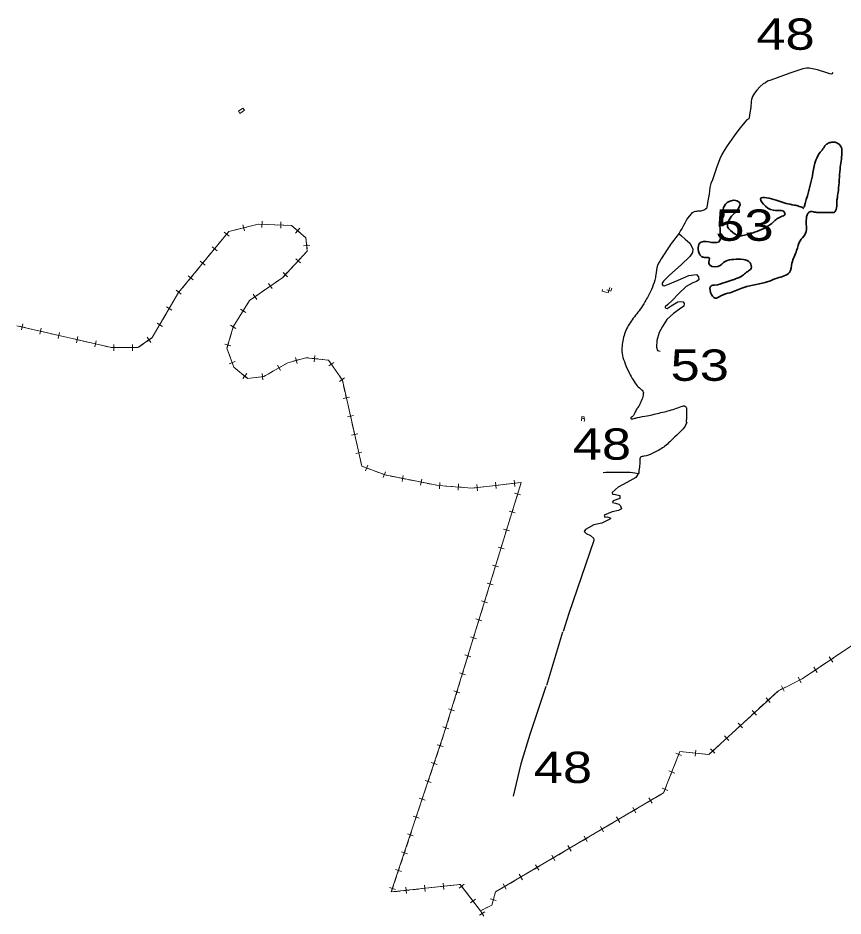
# Model space of a CAD drawing. Extents: x 476989 to 498418, y 4381813 to 4416555.
# Drawn here: x 485528 to 486843, y 4382275 to 4383707 of the extents above; entities that cross this region are included whole.
import ezdxf

# ---------------------------------------------------------------- set-up
doc = ezdxf.new("R2010")
doc.units = 0
doc.header["$LTSCALE"] = 20
doc.linetypes.add('MEDIUM_DASHED', pattern=[4.5, 3, -1.5])
for name, color, linetype, lineweight in [('13', 7, 'Continuous', 13), ('34', 7, 'Continuous', 13), ('48', 7, 'MEDIUM_DASHED', 13), ('6', 7, 'Continuous', 25)]:
    doc.layers.add(name, color=color, linetype=linetype, lineweight=lineweight)

msp = doc.modelspace()

# ---------------------------------------------------------------- linework, layer by layer
at = {"layer": '13', "lineweight": 35}
msp.add_spline([(486780.88, 4383404.79), (486794.13, 4383455.03), (486806.75, 4383492.74), (486812.33, 4383499.64), (486814.71, 4383503.51), (486819.41, 4383506.81), (486825.21, 4383508.61), (486829.49, 4383508.62), (486831.66, 4383508.22), (486834.79, 4383506.67), (486839.23, 4383502.48), (486841.25, 4383491.57), (486838.33, 4383465.65), (486835.59, 4383431.7), (486834, 4383420.31), (486833.25, 4383414.77), (486832.97, 4383406.37), (486832.3, 4383401.5), (486829.47, 4383397.12), (486823.83, 4383396.67), (486809.94, 4383396.27), (486802.97, 4383396.6), (486796, 4383397.37), (486791.44, 4383398.19), (486788.79, 4383396.8), (486785.88, 4383392.64), (486784.6, 4383386.95), (486784.53, 4383376.98), (486784.84, 4383372.17), (486782.2, 4383361.03), (486774.71, 4383351.45), (486769.08, 4383335.85), (486761.59, 4383315.77), (486757.7, 4383301.05), (486738.21, 4383291.87), (486723.87, 4383286.22), (486684.72, 4383277.1), (486662.99, 4383268.56), (486648.14, 4383263.67), (486639.3, 4383259.75), (486632.91, 4383279.8), (486638.33, 4383280.62), (486654.82, 4383284.96), (486667.34, 4383289.06), (486684.49, 4383297.14), (486691.09, 4383302.53), (486696.41, 4383307.18), (486694.82, 4383316.43), (486684.24, 4383321.46), (486669.01, 4383321.68), (486655.38, 4383318.57), (486643.48, 4383310.34), (486629.22, 4383315.27), (486629.5, 4383324.04), (486622.3, 4383324.82), (486616.85, 4383326.7), (486612.21, 4383337.87), (486614.37, 4383347.45), (486644.42, 4383349.27), (486649.2, 4383384.92), (486651.66, 4383388.63), (486652.89, 4383395.9), (486652.14, 4383401.38), (486671.78, 4383415.81), (486678.55, 4383411.44), (486675.33, 4383401.28), (486669.84, 4383395.35), (486659.1, 4383373.67), (486670.12, 4383362.71), (486675.25, 4383359.48), (486683.36, 4383359.82), (486702.12, 4383364.88), (486729.49, 4383379.19), (486744.12, 4383389.71), (486750.48, 4383393.52), (486749.77, 4383396.53), (486731.96, 4383399.94), (486712.51, 4383419.8), (486725.33, 4383419.24), (486752.3, 4383411.05), (486765.39, 4383408.24), (486770.85, 4383407.04), (486780.7, 4383403.07)], degree=3, dxfattribs=at)
at = {"layer": '34'}
for p, q in [((485882.86, 4383370.82), (485892.55, 4383373.29)), ((485886.47, 4383376.9), (485888.94, 4383367.21)), ((485897.4, 4383374.53), (485907.09, 4383377)), ((485911.95, 4383377.96), (485921.94, 4383377.59)), ((485917.13, 4383382.77), (485916.76, 4383372.78)), ((485926.94, 4383377.4), (485936.93, 4383377.02)), ((485941.92, 4383376.83), (485951.91, 4383376.46)), ((485947.1, 4383381.64), (485946.73, 4383371.65)), ((485856.63, 4383364.92), (485864.34, 4383358.56)), ((485857.31, 4383357.88), (485863.67, 4383365.6)), ((485868.34, 4383367.11), (485878.03, 4383369.58)), ((485969.96, 4383370.82), (485977.5, 4383364.26)), ((485977.01, 4383371.31), (485970.45, 4383363.77)), ((485847.77, 4383346.32), (485854.13, 4383354.03)), ((485993.15, 4383344.13), (485983.2, 4383343.18)), ((485987.7, 4383348.63), (485988.65, 4383338.68)), ((485828.69, 4383323.18), (485835.05, 4383330.9)), ((485837.55, 4383341.78), (485845.26, 4383335.42)), ((485838.22, 4383334.75), (485844.59, 4383342.46)), ((485988.11, 4383334.04), (485981.31, 4383326.71)), ((485818.47, 4383318.65), (485826.18, 4383312.29)), ((485819.14, 4383311.61), (485825.5, 4383319.32)), ((485978.17, 4383315.99), (485970.84, 4383322.8)), ((485977.91, 4383323.06), (485971.11, 4383315.73)), ((485809.6, 4383300.05), (485815.97, 4383307.76)), ((485957.76, 4383294.01), (485950.44, 4383300.82)), ((485957.5, 4383301.08), (485950.7, 4383293.75)), ((485967.7, 4383312.07), (485960.9, 4383304.74)), ((485799.38, 4383295.51), (485807.1, 4383289.15)), ((485800.06, 4383288.47), (485806.42, 4383296.19)), ((485946.74, 4383290.73), (485938.54, 4383285)), ((485780.3, 4383272.38), (485788.02, 4383266.01)), ((485790.52, 4383276.91), (485796.89, 4383284.62)), ((485922.15, 4383273.56), (485913.95, 4383267.83)), ((485934.45, 4383282.15), (485926.25, 4383276.42)), ((485933.21, 4383275.18), (485927.49, 4383283.38)), ((485774.05, 4383251.95), (485779.09, 4383260.59)), ((485909.86, 4383264.98), (485901.66, 4383259.25)), ((485908.62, 4383258.02), (485902.9, 4383266.22)), ((485764.7, 4383245.83), (485773.33, 4383240.79)), ((485766.5, 4383238.99), (485771.54, 4383247.63)), ((485889.47, 4383243.84), (485884.21, 4383235.33)), ((485758.94, 4383226.05), (485763.98, 4383234.68)), ((485881.57, 4383231.08), (485876.31, 4383222.58)), ((485891.09, 4383236.95), (485882.59, 4383242.22)), ((485529.63, 4383215.16), (485539.37, 4383212.9)), ((485535.63, 4383218.9), (485533.37, 4383209.16)), ((485749.59, 4383219.93), (485758.22, 4383214.89)), ((485751.39, 4383213.09), (485756.42, 4383221.73)), ((485875.3, 4383211.45), (485866.8, 4383216.72)), ((485544.24, 4383211.77), (485553.99, 4383209.51)), ((485558.85, 4383208.39), (485568.59, 4383206.13)), ((485564.85, 4383212.13), (485562.59, 4383202.39)), ((485573.46, 4383205), (485583.2, 4383202.74)), ((485588.06, 4383201.61), (485597.8, 4383199.36)), ((485594.06, 4383205.36), (485591.8, 4383195.61)), ((485743.83, 4383200.14), (485748.87, 4383208.78)), ((485868.21, 4383204.5), (485865.39, 4383194.91)), ((485602.67, 4383198.23), (485612.42, 4383195.97)), ((485617.28, 4383194.84), (485627.02, 4383192.58)), ((485623.28, 4383198.58), (485621.02, 4383188.84)), ((485631.89, 4383191.46), (485641.63, 4383189.2)), ((485646.49, 4383188.07), (485656.23, 4383185.81)), ((485652.49, 4383191.81), (485650.23, 4383182.07)), ((485680.67, 4383186), (485680.67, 4383176)), ((485710.66, 4383186), (485710.66, 4383176)), ((485720.37, 4383181.95), (485728.58, 4383187.66)), ((485732.67, 4383190.51), (485740.88, 4383196.22)), ((485733.92, 4383197.47), (485739.63, 4383189.26)), ((485867.36, 4383183.91), (485857.77, 4383186.74)), ((485863.98, 4383190.12), (485861.16, 4383180.53)), ((485661.11, 4383184.68), (485670.85, 4383182.43)), ((485690.67, 4383181), (485700.67, 4383181)), ((485705.66, 4383181), (485715.66, 4383181)), ((485862.53, 4383175.82), (485865.97, 4383166.43)), ((485874.11, 4383158.78), (485864.72, 4383155.33)), ((485867.69, 4383161.75), (485871.13, 4383152.36)), ((485966.62, 4383159.38), (485976.26, 4383162.04)), ((485970.11, 4383165.53), (485972.77, 4383155.89)), ((485995.79, 4383164.02), (486005.73, 4383162.92)), ((486001.31, 4383168.44), (486000.21, 4383158.5)), ((486010.7, 4383162.37), (486020.64, 4383161.26)), ((486031.43, 4383157.56), (486023.19, 4383151.89)), ((486024.48, 4383158.85), (486030.15, 4383150.61)), ((485873.92, 4383148.43), (485881.66, 4383142.09)), ((485926.81, 4383138.94), (485935.46, 4383143.95)), ((485939.78, 4383146.45), (485948.44, 4383151.46)), ((485941.6, 4383153.29), (485946.61, 4383144.63)), ((486032.98, 4383146.48), (486038.64, 4383138.24)), ((485885.53, 4383138.93), (485893.27, 4383132.6)), ((485892.56, 4383139.64), (485886.23, 4383131.9)), ((485898.02, 4383132.46), (485907.96, 4383133.61)), ((485917.31, 4383139.72), (485918.46, 4383129.79)), ((486048.42, 4383132.84), (486040.18, 4383127.18)), ((486046.94, 4383120.44), (486049.14, 4383110.69)), ((486056.22, 4383102.05), (486046.47, 4383099.84)), ((486050.24, 4383105.82), (486052.45, 4383096.07)), ((486053.55, 4383091.19), (486055.76, 4383081.44)), ((486062.84, 4383072.8), (486053.09, 4383070.59)), ((486056.86, 4383076.57), (486059.07, 4383066.82)), ((486060.17, 4383061.94), (486062.38, 4383052.19)), ((486069.46, 4383043.55), (486059.71, 4383041.34)), ((486063.48, 4383047.32), (486065.69, 4383037.57)), ((486066.79, 4383032.69), (486069, 4383022.94)), ((486076.08, 4383014.3), (486066.33, 4383012.09)), ((486070.1, 4383018.07), (486072.31, 4383008.32)), ((486073.41, 4383003.44), (486075.62, 4382993.69)), ((486079.05, 4382990.85), (486088.4, 4382987.31)), ((486085.49, 4382993.75), (486081.95, 4382984.4)), ((486093.08, 4382985.54), (486102.43, 4382982)), ((486113.54, 4382983.14), (486110, 4382973.79)), ((486121.52, 4382976.3), (486131.32, 4382974.34)), ((486136.22, 4382973.36), (486146.02, 4382971.4)), ((486142.1, 4382977.28), (486140.14, 4382967.47)), ((486171.51, 4382971.4), (486169.55, 4382961.59)), ((486150.93, 4382970.41), (486160.73, 4382968.45)), ((486165.63, 4382967.47), (486175.43, 4382965.51)), ((486180.33, 4382964.53), (486190.14, 4382962.57)), ((486200.34, 4382965.84), (486199.6, 4382955.87)), ((486209.94, 4382960.12), (486219.91, 4382959.38)), ((486224.89, 4382959.01), (486234.86, 4382958.27)), ((486230.25, 4382963.63), (486229.51, 4382953.65)), ((486239.85, 4382957.9), (486249.82, 4382957.16)), ((486254.79, 4382957.32), (486264.72, 4382958.47)), ((486259.18, 4382962.86), (486260.33, 4382952.93)), ((486269.69, 4382959.04), (486279.62, 4382960.19)), ((486284.58, 4382960.76), (486294.51, 4382961.91)), ((486288.97, 4382966.3), (486290.12, 4382956.37)), ((486299.48, 4382962.48), (486309.42, 4382963.62)), ((486314.37, 4382964.2), (486324.31, 4382965.34)), ((486318.77, 4382969.74), (486319.91, 4382959.8)), ((486329.13, 4382946.12), (486319.57, 4382949.05)), ((486325.82, 4382952.37), (486322.89, 4382942.81)), ((486321.42, 4382938.03), (486318.49, 4382928.47)), ((486320.34, 4382917.45), (486310.78, 4382920.38)), ((486317.02, 4382923.7), (486314.09, 4382914.14)), ((486312.63, 4382909.36), (486309.69, 4382899.8)), ((486311.54, 4382888.78), (486301.98, 4382891.71)), ((486308.23, 4382895.02), (486305.3, 4382885.46)), ((486303.83, 4382880.68), (486300.9, 4382871.12)), ((486302.75, 4382860.11), (486293.19, 4382863.04)), ((486299.44, 4382866.35), (486296.5, 4382856.79)), ((486295.04, 4382852.01), (486292.1, 4382842.45)), ((486293.95, 4382831.44), (486284.39, 4382834.37)), ((486290.64, 4382837.68), (486287.71, 4382828.12)), ((486286.24, 4382823.34), (486283.31, 4382813.78)), ((486285.16, 4382802.76), (486275.6, 4382805.7)), ((486281.85, 4382809.01), (486278.91, 4382799.45)), ((486277.45, 4382794.67), (486274.51, 4382785.11)), ((486276.37, 4382774.09), (486266.81, 4382777.02)), ((486273.05, 4382780.34), (486270.12, 4382770.78)), ((486268.65, 4382766), (486265.72, 4382756.44)), ((486267.57, 4382745.42), (486258.01, 4382748.35)), ((486264.26, 4382751.67), (486261.32, 4382742.11)), ((486259.86, 4382737.33), (486256.93, 4382727.77)), ((486258.78, 4382716.75), (486249.22, 4382719.68)), ((486255.46, 4382723), (486252.53, 4382713.44)), ((486251.06, 4382708.65), (486248.13, 4382699.09)), ((486249.98, 4382688.08), (486240.42, 4382691.01)), ((486246.67, 4382694.32), (486243.74, 4382684.76)), ((486828.14, 4382686.56), (486819.83, 4382681)), ((486826.77, 4382679.63), (486821.2, 4382687.94)), ((486840.6, 4382694.9), (486832.29, 4382689.34)), ((486242.27, 4382679.98), (486239.34, 4382670.42)), ((486801.84, 4382662.94), (486796.28, 4382671.25)), ((486815.67, 4382678.22), (486807.36, 4382672.66)), ((486241.19, 4382659.41), (486231.63, 4382662.34)), ((486237.87, 4382665.65), (486234.94, 4382656.09)), ((486790.75, 4382661.54), (486782.44, 4382655.97)), ((486803.22, 4382669.88), (486794.91, 4382664.32)), ((486233.47, 4382651.31), (486230.54, 4382641.75)), ((486749.26, 4382633.04), (486744.79, 4382641.98)), ((486764.9, 4382646.45), (486755.96, 4382641.98)), ((486776.08, 4382646.45), (486771.61, 4382655.4)), ((486232.39, 4382630.73), (486222.83, 4382633.67)), ((486229.08, 4382636.98), (486226.15, 4382627.42)), ((486738.42, 4382632.55), (486731.05, 4382625.78)), ((486751.49, 4382639.75), (486742.55, 4382635.28)), ((486224.68, 4382622.64), (486221.75, 4382613.08)), ((486727.38, 4382622.4), (486720.02, 4382615.64)), ((486727.08, 4382615.34), (486720.32, 4382622.7)), ((486223.6, 4382602.06), (486214.04, 4382605)), ((486220.28, 4382608.31), (486217.35, 4382598.75)), ((486705.3, 4382602.11), (486697.93, 4382595.35)), ((486705, 4382595.05), (486698.23, 4382602.41)), ((486716.34, 4382612.25), (486708.97, 4382605.49)), ((486215.89, 4382593.97), (486212.95, 4382584.41)), ((486694.25, 4382591.96), (486686.89, 4382585.2)), ((486214.8, 4382573.39), (486205.24, 4382576.32)), ((486211.49, 4382579.64), (486208.56, 4382570.08)), ((486672.17, 4382571.67), (486664.81, 4382564.9)), ((486683.22, 4382581.82), (486675.85, 4382575.05)), ((486682.92, 4382574.76), (486676.15, 4382582.12)), ((486661.13, 4382561.53), (486653.77, 4382554.76)), ((486660.83, 4382554.46), (486654.07, 4382561.83)), ((486205.52, 4382544.75), (486196.03, 4382547.91)), ((486202.36, 4382551.07), (486199.2, 4382541.59)), ((486638.75, 4382534.17), (486631.99, 4382541.53)), ((486650.09, 4382551.38), (486642.73, 4382544.61)), ((486197.61, 4382536.84), (486194.45, 4382527.36)), ((486585.8, 4382530.46), (486576.49, 4382534.13)), ((486582.98, 4382536.94), (486579.31, 4382527.64)), ((486597.84, 4382535.39), (486587.9, 4382536.47)), ((486612.76, 4382533.77), (486602.81, 4382534.85)), ((486607.24, 4382529.34), (486608.33, 4382539.28)), ((486627.66, 4382532.15), (486617.72, 4382533.23)), ((486639.05, 4382541.24), (486631.69, 4382534.47)), ((486196.04, 4382516.3), (486186.55, 4382519.46)), ((486192.87, 4382522.62), (486189.71, 4382513.14)), ((486577.48, 4382522.99), (486573.82, 4382513.68)), ((486188.13, 4382508.39), (486184.97, 4382498.91)), ((486574.81, 4382502.56), (486565.5, 4382506.22)), ((486571.99, 4382509.04), (486568.32, 4382499.74)), ((486186.55, 4382487.85), (486177.07, 4382491.01)), ((486183.39, 4382494.17), (486180.23, 4382484.69)), ((486566.49, 4382495.09), (486562.82, 4382485.78)), ((486178.65, 4382479.94), (486175.49, 4382470.46)), ((486563.81, 4382474.65), (486554.51, 4382478.32)), ((486560.99, 4382481.14), (486557.33, 4382471.83)), ((486177.07, 4382459.4), (486167.58, 4382462.56)), ((486173.91, 4382465.72), (486170.74, 4382456.23)), ((486540.55, 4382461.3), (486531.94, 4382456.22)), ((486538.79, 4382454.46), (486533.71, 4382463.07)), ((486553.47, 4382468.92), (486544.85, 4382463.84)), ((486169.16, 4382451.49), (486166, 4382442)), ((486514.72, 4382446.07), (486506.1, 4382440.99)), ((486512.95, 4382439.23), (486507.87, 4382447.84)), ((486527.63, 4382453.69), (486519.02, 4382448.61)), ((486167.59, 4382430.95), (486158.1, 4382434.11)), ((486164.42, 4382437.27), (486161.26, 4382427.78)), ((486488.88, 4382430.84), (486480.27, 4382425.76)), ((486487.12, 4382424), (486482.04, 4382432.61)), ((486501.8, 4382438.45), (486493.18, 4382433.38)), ((486159.68, 4382423.04), (486156.52, 4382413.55)), ((486463.05, 4382415.61), (486454.43, 4382410.53)), ((486461.28, 4382408.76), (486456.2, 4382417.38)), ((486475.96, 4382423.22), (486467.35, 4382418.15)), ((486158.1, 4382402.49), (486148.62, 4382405.66)), ((486154.94, 4382408.82), (486151.78, 4382399.33)), ((486437.21, 4382400.38), (486428.6, 4382395.3)), ((486435.45, 4382393.53), (486430.37, 4382402.15)), ((486450.13, 4382407.99), (486441.51, 4382402.91)), ((486150.2, 4382394.59), (486147.03, 4382385.1)), ((486411.38, 4382385.15), (486402.77, 4382380.07)), ((486409.61, 4382378.3), (486404.53, 4382386.92)), ((486424.29, 4382392.76), (486415.68, 4382387.68)), ((486148.62, 4382374.04), (486139.13, 4382377.21)), ((486145.46, 4382380.37), (486142.29, 4382370.88)), ((486385.55, 4382369.92), (486376.93, 4382364.84)), ((486383.78, 4382363.07), (486378.7, 4382371.69)), ((486398.46, 4382377.53), (486389.84, 4382372.45)), ((486140.71, 4382366.14), (486137.55, 4382356.65)), ((486357.94, 4382347.84), (486352.86, 4382356.46)), ((486372.62, 4382362.3), (486364.01, 4382357.22)), ((486139.13, 4382345.59), (486129.65, 4382348.75)), ((486135.97, 4382351.92), (486132.81, 4382342.43)), ((486332.11, 4382332.61), (486327.03, 4382341.23)), ((486346.79, 4382347.07), (486338.18, 4382341.99)), ((486359.71, 4382354.69), (486351.1, 4382349.61)), ((486131.23, 4382337.69), (486128.07, 4382328.2)), ((486205.9, 4382327.07), (486206.98, 4382317.13)), ((486320.96, 4382331.84), (486312.34, 4382326.76)), ((486333.88, 4382339.46), (486325.26, 4382334.38)), ((486129.65, 4382317.14), (486120.16, 4382320.3)), ((486126.49, 4382323.47), (486123.33, 4382313.98)), ((486126.94, 4382313.43), (486136.89, 4382314.51)), ((486141.85, 4382315.06), (486151.79, 4382316.14)), ((486146.27, 4382320.57), (486147.36, 4382310.63)), ((486156.76, 4382316.68), (486166.7, 4382317.77)), ((486171.66, 4382318.31), (486181.6, 4382319.39)), ((486176.09, 4382323.82), (486177.17, 4382313.88)), ((486186.57, 4382319.93), (486196.51, 4382321.02)), ((486201.47, 4382321.56), (486211.41, 4382322.65)), ((486216.38, 4382323.19), (486226.32, 4382324.27)), ((486238.96, 4382325.43), (486231.01, 4382319.36)), ((486241.05, 4382314.44), (486247.11, 4382306.49)), ((486308.04, 4382324.23), (486299.43, 4382319.15)), ((486306.27, 4382317.38), (486301.2, 4382325.99)), ((486257.14, 4382301.57), (486249.18, 4382295.51)), ((486250.13, 4382302.52), (486256.19, 4382294.56)), ((486290.27, 4382299.24), (486280.65, 4382301.98)), ((486286.83, 4382305.42), (486284.09, 4382295.8)), ((486259.22, 4382290.59), (486265, 4382283)), ((486268.66, 4382284.83), (486265, 4382283)), ((486282.07, 4382291.53), (486273.12, 4382287.06)), ((486271.92, 4382281.59), (486263.58, 4382276.08)), ((486265, 4382283), (486270.51, 4382274.66))]:
    msp.add_line(p, q, dxfattribs=at)
for points in [[(485526, 4383216), (485677, 4383181), (485719, 4383181), (485742, 4383197), (485784, 4383269), (485864, 4383366), (485911, 4383378), (485964, 4383376), (485987, 4383356), (485989, 4383335), (485950, 4383293), (485897, 4383256), (485871, 4383214), (485861, 4383180), (485872, 4383150), (485894, 4383132), (485920, 4383135), (485958, 4383157), (485987, 4383165), (486023, 4383161), (486045, 4383129), (486076, 4382992), (486113, 4382978), (486198, 4382961), (486252, 4382957), (486330, 4382966), (486207, 4382565), (486123, 4382313), (486233, 4382325), (486265, 4382283)], [(485956.91, 4383376.27), (485964, 4383376), (485966.19, 4383374.1)], [(485981.27, 4383360.98), (485987, 4383356), (485987.23, 4383353.6)], [(487676.62, 4383311.4), (487577, 4383232), (487304, 4383028), (487077, 4382869), (487054, 4382844), (487031, 4382851), (487023, 4382817), (486778, 4382653), (486740, 4382634), (486629, 4382532), (486583, 4382537), (486557, 4382471), (486289, 4382313), (486283, 4382292), (486265, 4382283)], [(485781.61, 4383264.9), (485784, 4383269), (485787.34, 4383273.05)], [(485897.56, 4383256.39), (485897, 4383256), (485892.1, 4383248.08)], [(485873.68, 4383218.34), (485871, 4383214), (485869.62, 4383209.3)], [(485675.71, 4383181.3), (485677, 4383181), (485685.67, 4383181)], [(485952.76, 4383153.97), (485958, 4383157), (485961.81, 4383158.05)], [(485981.08, 4383163.37), (485987, 4383165), (485990.83, 4383164.57)], [(485912.92, 4383134.18), (485920, 4383135), (485922.48, 4383136.44)], [(486041.47, 4383134.13), (486045, 4383129), (486045.83, 4383125.32)], [(486107.1, 4382980.23), (486113, 4382978), (486116.62, 4382977.28)], [(486195.03, 4382961.59), (486198, 4382961), (486204.96, 4382960.48)], [(486329.27, 4382965.92), (486330, 4382966), (486327.28, 4382957.14)], [(486778.3, 4382653.2), (486778, 4382653), (486769.37, 4382648.69)], [(486207.09, 4382565.3), (486207, 4382565), (486203.94, 4382555.81)], [(486231.29, 4382324.81), (486233, 4382325), (486238.02, 4382318.42)], [(486295.12, 4382316.61), (486289, 4382313), (486288.2, 4382310.22)]]:
    msp.add_lwpolyline(points, dxfattribs=at)
at = {"layer": '48'}
msp.add_line((486429.89, 4383067.74), (486426.6, 4383068.42), dxfattribs=at)
msp.add_lwpolyline([(485881.83, 4383554.31), (485889.05, 4383559.53), (485886.53, 4383563.02), (485879.31, 4383557.8)], close=True, dxfattribs=at)
for points in [[(486474.49, 4383275.89), (486473.11, 4383271.21), (486469.61, 4383272.22), (486468.54, 4383268.53), (486459.21, 4383271.2), (486459.85, 4383273.46)], [(486471.29, 4383276.64), (486469.61, 4383272.22), (486466.47, 4383273.39)], [(486426.03, 4383064.26), (486426.95, 4383071), (486430.31, 4383070.49), (486429.89, 4383067.74), (486431.31, 4383067.49), (486430.58, 4383063.35)]]:
    msp.add_lwpolyline(points, dxfattribs=at)
at = {"layer": '6'}
msp.add_line((486396.11, 4382727.09), (486370.16, 4382642.32), dxfattribs=at)
for points in [[(486826.89, 4383619.48), (486825.23, 4383617.64), (486823.45, 4383617.32), (486817.23, 4383619.19), (486802.39, 4383623.82), (486794.27, 4383625.68), (486789.22, 4383626.87), (486786.8, 4383626.58), (486784.88, 4383626.6), (486778.78, 4383625.44), (486774.01, 4383623.98), (486758.45, 4383618.79), (486728.02, 4383607.73), (486722.8, 4383605.72), (486719.23, 4383603.45), (486715.99, 4383601.58), (486710.95, 4383597.61), (486705.68, 4383591.8), (486702.17, 4383586.52), (486698.61, 4383581.29), (486697.25, 4383576.87), (486696.73, 4383573.56), (486695.83, 4383564.12), (486694.52, 4383555.26), (486693.37, 4383548.23), (486692.99, 4383545.88), (486689.77, 4383544.13), (486683.85, 4383537.38), (486677.07, 4383528.72), (486669.63, 4383518.52), (486658.36, 4383502.75), (486653.4, 4383495.54), (486650.12, 4383489.18), (486646.74, 4383482.31), (486641.62, 4383467.51), (486636.62, 4383453.34), (486634.83, 4383448.37), (486632.39, 4383442.5), (486630.76, 4383436.09), (486629.41, 4383425.92), (486627.6, 4383415.24), (486626.45, 4383407.65), (486625.31, 4383403), (486623.23, 4383401.09), (486621.01, 4383400.11), (486616.4, 4383398.76)], [(486581.36, 4383363.04), (486585.6, 4383359.47), (486591.33, 4383354.08), (486598.77, 4383347.36), (486603.73, 4383338.47), (486602.89, 4383332.66), (486599.1, 4383326.49), (486584.93, 4383313.02), (486566.33, 4383296.79), (486556.72, 4383287.17), (486554.58, 4383284.05), (486554.88, 4383281.74), (486555.64, 4383280.33), (486557.96, 4383279.81), (486563.98, 4383281.74), (486580.17, 4383288.52), (486597.42, 4383296.04), (486609.35, 4383297.86), (486612.87, 4383293.86), (486613.06, 4383288.93), (486609.6, 4383286.5), (486603.52, 4383284.14), (486593.03, 4383278.36), (486580.51, 4383266.34), (486571.33, 4383256.67), (486563.64, 4383249.94), (486559.74, 4383245.96), (486559.63, 4383245.23), (486560.47, 4383243.73), (486562.47, 4383243.55), (486569.19, 4383247.72), (486579.91, 4383253.86), (486584.04, 4383254.81), (486588.35, 4383254.3), (486589.81, 4383251.21), (486589.41, 4383247.2), (486582.25, 4383242.17), (486572.68, 4383235.58), (486562.22, 4383225.85), (486555.2, 4383214.86), (486549.89, 4383205.03), (486546.16, 4383192.21), (486545.59, 4383181.98), (486547.39, 4383176.69), (486551.61, 4383175.26)], [(486517.39, 4382981.15), (486512.54, 4382973.9), (486498.53, 4382965.91), (486484.52, 4382958.57), (486475.19, 4382949.91), (486475.85, 4382947.24), (486480.52, 4382946.58), (486487.19, 4382945.24), (486487.19, 4382940.58), (486476.52, 4382936.58), (486475.85, 4382933.91), (486480.52, 4382933.24), (486485.86, 4382931.24), (486488.53, 4382928.58), (486489.86, 4382923.91), (486485.19, 4382921.25), (486475.19, 4382919.25), (486462.51, 4382913.91), (486463.18, 4382910.58), (486467.85, 4382911.25), (486473.18, 4382909.25), (486471.18, 4382907.25), (486458.51, 4382901.25), (486445.84, 4382898.58), (486437.16, 4382893.92), (486432.49, 4382891.25), (486430.49, 4382887.92), (486433.83, 4382884.59), (486440.5, 4382881.25), (486445.17, 4382877.25), (486445.84, 4382873.92)], [(486517.24, 4382979.78), (486511.21, 4382980.64), (486503.53, 4382981.64), (486492.53, 4382981.64), (486482.86, 4382981.97), (486465.18, 4382981.64), (486460.51, 4382981.31)], [(486445.81, 4382873.41), (486406.24, 4382757.15), (486396.79, 4382728.38)], [(486369.4, 4382640.61), (486343.6, 4382563.91), (486329.34, 4382517.49), (486317.11, 4382465.75)]]:
    msp.add_lwpolyline(points, dxfattribs=at)
for points in [[(486616.4, 4383398.76), (486609.53, 4383398.32), (486605.76, 4383397.51), (486603.64, 4383396.68), (486601.06, 4383394.53), (486581.77, 4383363.75), (486567.92, 4383345.34), (486555.49, 4383325.84), (486547.31, 4383311.93), (486544.63, 4383297.26), (486542.93, 4383288.69), (486537.77, 4383273.81), (486528.83, 4383256.87), (486521.61, 4383244.78), (486506.85, 4383225.48), (486495.82, 4383205.81), (486490.76, 4383183.12), (486490.75, 4383171.7), (486494.48, 4383158.89), (486500.87, 4383143.53), (486507.02, 4383132), (486513.34, 4383122.31), (486520.6, 4383114.98), (486524.69, 4383110.49), (486524.72, 4383107.37), (486523.98, 4383102.8), (486520.48, 4383093.44), (486518.01, 4383088.42), (486514.34, 4383083.16), (486511.09, 4383077.17), (486509.02, 4383072.98), (486506.76, 4383070.57), (486504.86, 4383068.89), (486504.98, 4383068.05), (486506.45, 4383067.29), (486509.87, 4383067.88), (486515.23, 4383069.39), (486530.79, 4383072.38), (486552.79, 4383077.34), (486574.89, 4383083.42), (486585.15, 4383087.17), (486588.99, 4383088.06), (486590.1, 4383087.94), (486592.93, 4383085.95), (486593.37, 4383080.97), (486593.38, 4383076.71), (486593.42, 4383068.62), (486592.95, 4383062.34)], [(486593.85, 4383062.23), (486591.36, 4383055.96), (486583.58, 4383046.92), (486572.39, 4383036.05), (486557.19, 4383022.53), (486539.86, 4383012.5), (486525.54, 4383007.75), (486520.42, 4383006.25), (486519.2, 4383000.04), (486518.39, 4382990.6), (486517.24, 4382979.78)]]:
    msp.add_spline(points, degree=3, dxfattribs=at)

# ---------------------------------------------------------------- texts
at = {"layer": '13', "width": 1.25}
for s, p in [('48', (486704.87, 4383655.94)), ('53', (486639.46, 4383351.34)), ('53', (486568.21, 4383128.07)), ('48', (486412.2, 4383002.28)), ('48', (486350.15, 4382486.73))]:
    msp.add_text(s, height=50, dxfattribs=at).set_placement(p)

doc.saveas('drawing.dxf')
